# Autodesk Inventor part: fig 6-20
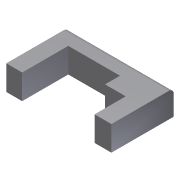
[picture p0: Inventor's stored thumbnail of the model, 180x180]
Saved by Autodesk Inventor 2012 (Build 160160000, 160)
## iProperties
Created: 2010-08
Part Number: fig 6-20
Document SubType Name: Modeling
Designer: CADSoft
Density: 1 g/cm^3
Material: Default
Author: CADSoft
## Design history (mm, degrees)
sketch "Sketch1"
  geometry: L1 (-25.394, 25.152)-(17.03, 25.152); L2 (17.03, 25.152)-(17.03, 0); L3 (-25.394, 0)-(-25.394, 25.152); L4 (10.242, 0)-(10.242, 12.576); L5 (10.242, 12.576)-(1.879, 12.576); L6 (1.879, 12.576)-(1.879, 18.606); L7 (1.879, 18.606)-(-18.97, 18.606); L8 (-18.97, 18.606)-(-18.97, 0); L9 (17.03, 0)-(10.242, 0); L10 (-18.97, 0)-(-25.394, 0); 1 further point
  constraints: 20 end point, 6 parallel, 4 perpendicular, 1 horizontal
extrude "Extrusion1" new body sketch "Sketch1" distance "d0" = 10; taper "d1" = 0 deg
fillet "Fillet1" dims "d2" = 2
body "Solid1"
